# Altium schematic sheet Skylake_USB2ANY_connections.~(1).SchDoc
size 431 x 279 mm; Date: Not shown in title block; ApprovedBy: Not shown in title block; CheckedBy: Not shown in title block; Author: Not shown in title block; CompanyName: Not shown in title block; Engineer: Not shown in title block; Organization: Not shown in title block; Address1: Not shown in title block; Address2: Not shown in title block; Address3: Not shown in title block; Address4: Not shown in title block; DocumentNumber: 1; Revision: Use project parameter SCH_Rev; SheetNumber: 7; SheetTotal: 9; PageSetup: Record=PageOptions|CenterHorizontal=True|CenterVertical=True|PrintScale=1.00|XCorrection=1.00|YCorrection=1.00|PrintKind=0|BorderSize=5000000|LeftOffset=0|BottomOffset=0|Orientation=2|PaperLength=1000|PaperWidth=1000|Scale=100|PaperSource=15|PrintQuality=600|MediaType=1|DitherType=10|PaperKind=Letter|PrintScaleMode=1
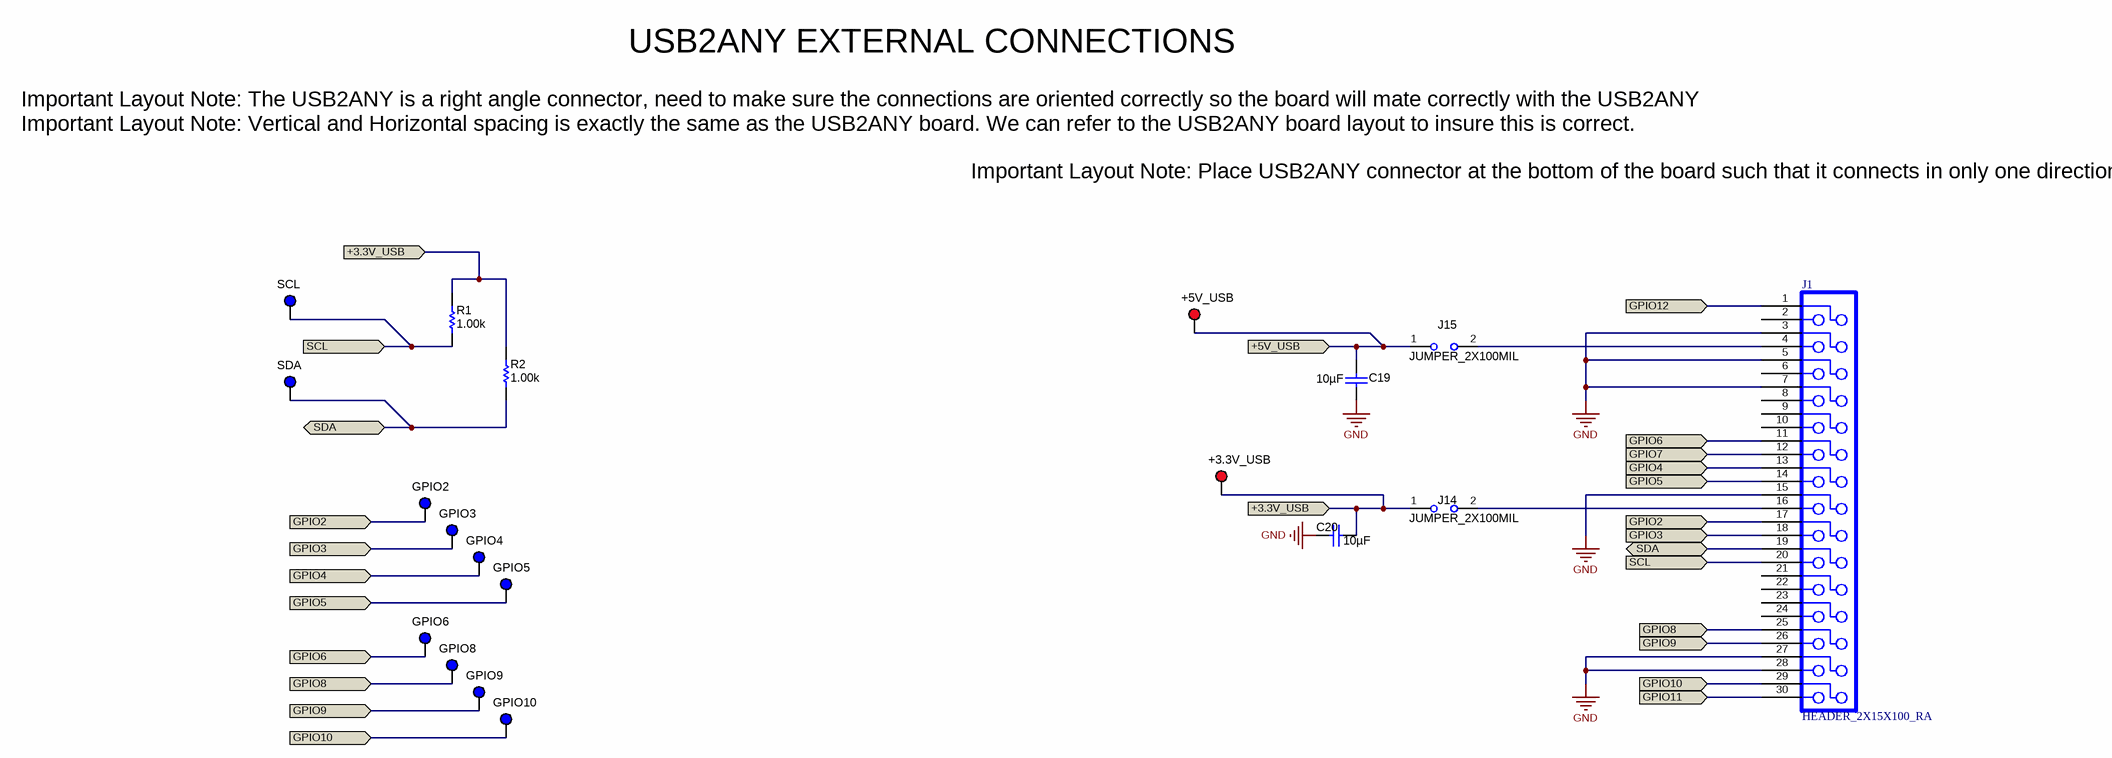
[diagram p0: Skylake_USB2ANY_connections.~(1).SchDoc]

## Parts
+3.3V_USB  5005  [Keystone5005]  (value not drawn)
+5V_USB  5005  [Keystone5005]  (value not drawn)
C19  ValueDisplayed: 10µF  [0805_HV]  (hidden comment: C0805C106K8PACTU)
C20  ValueDisplayed: 10µF  [0805_HV]  (hidden comment: C0805C106K8PACTU)
GPIO2  5122  [Keystone5122]  (value not drawn)
GPIO3  5122  [Keystone5122]  (value not drawn)
GPIO4  5122  [Keystone5122]  (value not drawn)
GPIO5  5122  [Keystone5122]  (value not drawn)
GPIO6  5122  [Keystone5122]  (value not drawn)
GPIO8  5122  [Keystone5122]  (value not drawn)
GPIO9  5122  [Keystone5122]  (value not drawn)
GPIO10  5122  [Keystone5122]  (value not drawn)
J1  HEADER_2X15X100_RA  [2530-5002UB]
J14  JUMPER_2X100MIL  [HDR100_1X2]
J15  JUMPER_2X100MIL  [HDR100_1X2]
R1  value 1.00k  [0402]  (hidden comment: CRCW04021K00FKED)
R2  value 1.00k  [0402]  (hidden comment: CRCW04021K00FKED)
SCL  5122  [Keystone5122]  (value not drawn)
SDA  5122  [Keystone5122]  (value not drawn)

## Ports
+3.3V_USB (in), +5V_USB (in), GPIO2 (in), GPIO3 (in), GPIO4 (in), GPIO5 (in), GPIO6 (in), GPIO7 (in), GPIO8 (in), GPIO9 (in), GPIO10 (in), GPIO11 (in), GPIO12 (in), SCL (in), SDA (bidir)

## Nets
GND: C19.2 C20.2 J1.3 J1.5 J1.7 J1.15 J1.27 J1.28
+3.3V_USB: +3.3V_USB.1 C20.1 J14.1 R1.2 R2.2 ; port +3.3V_USB
+5V_USB: +5V_USB.1 C19.1 J15.1 ; port +5V_USB
GPIO2: GPIO2.1 J1.17 ; port GPIO2
GPIO3: GPIO3.1 J1.18 ; port GPIO3
GPIO4: GPIO4.1 J1.13 ; port GPIO4
GPIO5: GPIO5.1 J1.14 ; port GPIO5
GPIO6: GPIO6.1 J1.11 ; port GPIO6
GPIO7: J1.12 ; port GPIO7
GPIO8: GPIO8.1 J1.25 ; port GPIO8
GPIO9: GPIO9.1 J1.26 ; port GPIO9
GPIO10: GPIO10.1 J1.29 ; port GPIO10
GPIO11: J1.30 ; port GPIO11
GPIO12: J1.1 ; port GPIO12
SCL: J1.20 R1.1 SCL.1 ; port SCL
SDA: J1.19 R2.1 SDA.1 ; port SDA
NetJ1_4: J1.4 J15.2
NetJ1_16: J1.16 J14.2

Not connected (* = marked no-connect by the designer): J1 2 6 8 9 10 21 22 23 24

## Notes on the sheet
- USB2ANY EXTERNAL CONNECTIONS
- Important Layout Note: The USB2ANY is a right angle connector, need to make sure the connections are oriented correctly so the board will mate correctly with the USB2ANY
  Important Layout Note: Vertical and Horizontal spacing is exactly the same as the USB2ANY board. We can refer to the USB2ANY board layout to insure this is correct.
- Important Layout Note: Place USB2ANY connector at the bottom of the board such that it connects in only one direction

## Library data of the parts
+3.3V_USB +5V_USB = 5005: Test Point, Compact, Red, TH; Manufacturer: Keystone; CompType: Test Point Loop; U/M: EA
C19 C20 = C0805C106K8PACTU: CAP, CERM, 10uF, 10V, +/-10%, X5R, 0805; Manufacturer: Kemet; Polarized: N; CompType: Capacitor; U/M: EA; Cap_F: 0.00001; Tolerance_%: 10; ESR_Ohm: 0.003; Value1: 0.003 ohm; IRMS_A: 11.43; TaMin_C: -55; TaMax_C: 85; Cap_Case: 0805
GPIO2-GPIO6 GPIO8-GPIO10 SCL SDA = 5122: Test Point, Compact, Blue, TH; Manufacturer: Keystone; CompType: Test Point Loop; U/M: EA
J1 = HEADER_2X15X100_RA: Header, Male 2x15-pin,  100mil spacing (36-pin strip), Right-Angle; Manufacturer: 3M; area: 872100; Value: 2530-5002UB
J14 J15 = JUMPER_2X100MIL: Header, Male 2-pin, 100mil spacing,; Manufacturer: Sullins; PartNumber: PEC02SAAN; area: 20000; Value: PEC02SAAN
R1 R2 = CRCW04021K00FKED: RES, 1.00k ohm, 1%, 0.063W, 0402; Manufacturer: Vishay-Dale; CompType: Resistor; Res_ohm: 1000; Value_Code: 1k00; Tolerance_%: 1; Power_W: 0.063; VDC_V: 50; TempCo: 100 ppm/C; EIA_Code: E96; U/M: EA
